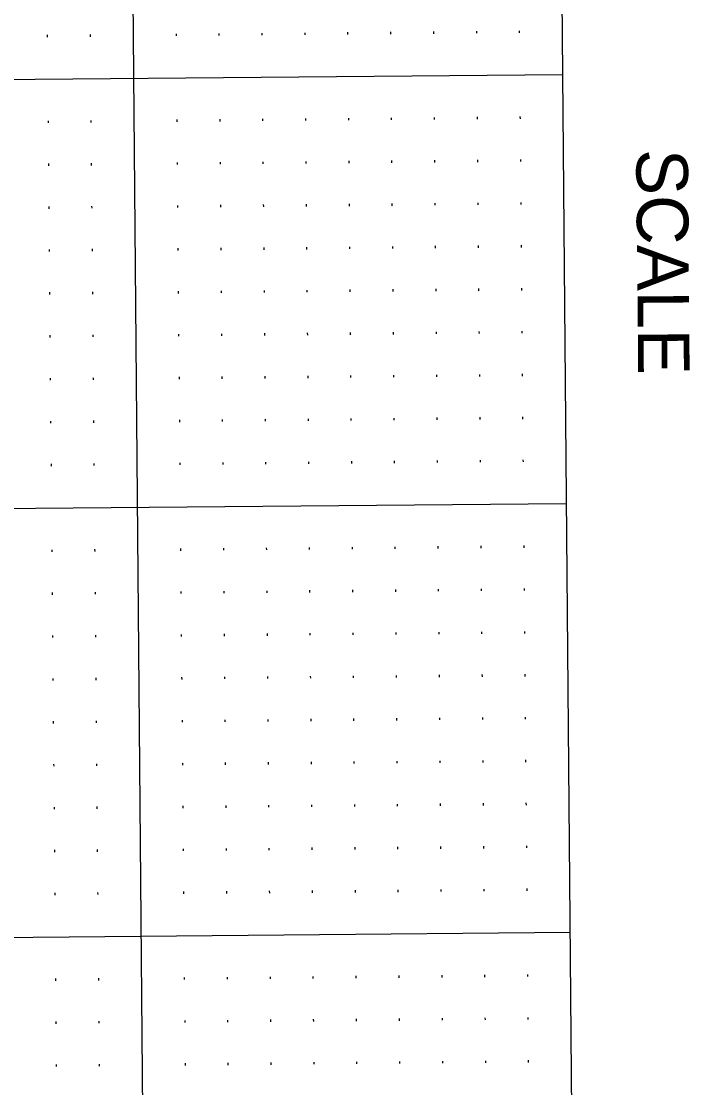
# Model space of a CAD drawing. Extents: x 2149873 to 2152007, y 140538 to 142349.
# Drawn here: x 2150424.8 to 2150502.7, y 140658.5 to 140782.7 of the extents above; entities that cross this region are included whole.
import ezdxf

# ---------------------------------------------------------------- set-up
doc = ezdxf.new("R2010")
doc.units = 0
for name, color, linetype in [('SHT_Profile_Grid_Major', 7, 'Continuous'), ('SHT_Profile_Grid_Minor', 7, 'Continuous'), ('SHT_Scale', 7, 'Continuous'), ('SHT_Sheet_Border', 7, 'Continuous')]:
    doc.layers.add(name, color=color, linetype=linetype)

msp = doc.modelspace()

# ---------------------------------------------------------------- linework, layer by layer
at = {"layer": 'SHT_Profile_Grid_Major'}
for p, q in [((2150425.71, 142163.57), (2150439.49, 140588.63)), ((2150012.87, 140772.4), (2150487.85, 140776.56)), ((2150088.3, 140723.06), (2150488.29, 140726.56)), ((2150088.74, 140673.06), (2150488.73, 140676.56))]:
    msp.add_line(p, q, dxfattribs=at)
at = {"layer": 'SHT_Profile_Grid_Minor'}
for p, q in [((2150472.81, 140781.55), (2150472.81, 140781.3)), ((2150477.81, 140781.6), (2150477.81, 140781.35)), ((2150482.81, 140781.64), (2150482.81, 140781.39)), ((2150427.81, 140781.16), (2150427.81, 140780.91)), ((2150432.81, 140781.2), (2150432.81, 140780.95)), ((2150442.81, 140781.29), (2150442.81, 140781.04)), ((2150447.81, 140781.34), (2150447.81, 140781.09)), ((2150452.81, 140781.38), (2150452.81, 140781.13)), ((2150457.81, 140781.42), (2150457.81, 140781.17)), ((2150462.81, 140781.47), (2150462.81, 140781.22)), ((2150467.81, 140781.51), (2150467.81, 140781.26)), ((2150477.89, 140771.6), (2150477.9, 140771.35)), ((2150482.89, 140771.64), (2150482.9, 140771.39)), ((2150427.9, 140771.16), (2150427.9, 140770.91)), ((2150432.9, 140771.2), (2150432.9, 140770.95)), ((2150442.9, 140771.29), (2150442.9, 140771.04)), ((2150447.9, 140771.34), (2150447.9, 140771.09)), ((2150452.9, 140771.38), (2150452.9, 140771.13)), ((2150457.9, 140771.42), (2150457.9, 140771.17)), ((2150462.9, 140771.47), (2150462.9, 140771.22)), ((2150467.89, 140771.51), (2150467.9, 140771.26)), ((2150472.89, 140771.55), (2150472.9, 140771.3)), ((2150482.94, 140766.64), (2150482.94, 140766.39)), ((2150427.94, 140766.16), (2150427.94, 140765.91)), ((2150432.94, 140766.2), (2150432.94, 140765.95)), ((2150442.94, 140766.29), (2150442.94, 140766.04)), ((2150447.94, 140766.34), (2150447.94, 140766.09)), ((2150452.94, 140766.38), (2150452.94, 140766.13)), ((2150457.94, 140766.42), (2150457.94, 140766.17)), ((2150462.94, 140766.47), (2150462.94, 140766.22)), ((2150467.94, 140766.51), (2150467.94, 140766.26)), ((2150472.94, 140766.55), (2150472.94, 140766.3)), ((2150477.94, 140766.6), (2150477.94, 140766.35)), ((2150482.98, 140761.64), (2150482.98, 140761.39)), ((2150427.98, 140761.16), (2150427.99, 140760.91)), ((2150432.98, 140761.2), (2150432.99, 140760.95)), ((2150442.98, 140761.29), (2150442.99, 140761.04)), ((2150447.98, 140761.34), (2150447.99, 140761.09)), ((2150452.98, 140761.38), (2150452.99, 140761.13)), ((2150457.98, 140761.42), (2150457.99, 140761.17)), ((2150462.98, 140761.47), (2150462.98, 140761.22)), ((2150467.98, 140761.51), (2150467.98, 140761.26)), ((2150472.98, 140761.56), (2150472.98, 140761.31)), ((2150477.98, 140761.6), (2150477.98, 140761.35)), ((2150428.03, 140756.16), (2150428.03, 140755.91)), ((2150433.03, 140756.21), (2150433.03, 140755.96)), ((2150443.03, 140756.29), (2150443.03, 140756.04)), ((2150448.03, 140756.34), (2150448.03, 140756.09)), ((2150453.03, 140756.38), (2150453.03, 140756.13)), ((2150458.03, 140756.42), (2150458.03, 140756.17)), ((2150463.03, 140756.47), (2150463.03, 140756.22)), ((2150468.03, 140756.51), (2150468.03, 140756.26)), ((2150473.03, 140756.56), (2150473.03, 140756.31)), ((2150478.03, 140756.6), (2150478.03, 140756.35)), ((2150483.03, 140756.64), (2150483.03, 140756.39)), ((2150428.07, 140751.16), (2150428.07, 140750.91)), ((2150433.07, 140751.21), (2150433.07, 140750.96)), ((2150443.07, 140751.29), (2150443.07, 140751.04)), ((2150448.07, 140751.34), (2150448.07, 140751.09)), ((2150453.07, 140751.38), (2150453.07, 140751.13)), ((2150458.07, 140751.42), (2150458.07, 140751.17)), ((2150463.07, 140751.47), (2150463.07, 140751.22)), ((2150468.07, 140751.51), (2150468.07, 140751.26)), ((2150473.07, 140751.56), (2150473.07, 140751.31)), ((2150478.07, 140751.6), (2150478.07, 140751.35)), ((2150483.07, 140751.64), (2150483.07, 140751.39)), ((2150428.12, 140746.16), (2150428.12, 140745.91)), ((2150433.12, 140746.21), (2150433.12, 140745.96)), ((2150443.11, 140746.29), (2150443.12, 140746.04)), ((2150448.11, 140746.34), (2150448.12, 140746.09)), ((2150453.11, 140746.38), (2150453.12, 140746.13)), ((2150458.11, 140746.42), (2150458.12, 140746.17)), ((2150463.11, 140746.47), (2150463.12, 140746.22)), ((2150468.11, 140746.51), (2150468.12, 140746.26)), ((2150473.11, 140746.56), (2150473.12, 140746.31)), ((2150478.11, 140746.6), (2150478.12, 140746.35)), ((2150483.11, 140746.64), (2150483.12, 140746.39)), ((2150428.16, 140741.16), (2150428.16, 140740.91)), ((2150433.16, 140741.21), (2150433.16, 140740.96)), ((2150443.16, 140741.29), (2150443.16, 140741.04)), ((2150448.16, 140741.34), (2150448.16, 140741.09)), ((2150453.16, 140741.38), (2150453.16, 140741.13)), ((2150458.16, 140741.42), (2150458.16, 140741.17)), ((2150463.16, 140741.47), (2150463.16, 140741.22)), ((2150468.16, 140741.51), (2150468.16, 140741.26)), ((2150473.16, 140741.56), (2150473.16, 140741.31)), ((2150478.16, 140741.6), (2150478.16, 140741.35)), ((2150483.16, 140741.64), (2150483.16, 140741.39)), ((2150428.2, 140736.16), (2150428.2, 140735.91)), ((2150433.2, 140736.21), (2150433.2, 140735.96)), ((2150443.2, 140736.29), (2150443.2, 140736.04)), ((2150448.2, 140736.34), (2150448.2, 140736.09)), ((2150453.2, 140736.38), (2150453.2, 140736.13)), ((2150458.2, 140736.42), (2150458.2, 140736.17)), ((2150463.2, 140736.47), (2150463.2, 140736.22)), ((2150468.2, 140736.51), (2150468.2, 140736.26)), ((2150473.2, 140736.56), (2150473.2, 140736.31)), ((2150478.2, 140736.6), (2150478.2, 140736.35)), ((2150483.2, 140736.64), (2150483.2, 140736.39)), ((2150428.25, 140731.16), (2150428.25, 140730.91)), ((2150433.25, 140731.21), (2150433.25, 140730.96)), ((2150443.25, 140731.29), (2150443.25, 140731.04)), ((2150448.25, 140731.34), (2150448.25, 140731.09)), ((2150453.25, 140731.38), (2150453.25, 140731.13)), ((2150458.25, 140731.42), (2150458.25, 140731.17)), ((2150463.25, 140731.47), (2150463.25, 140731.22)), ((2150468.25, 140731.51), (2150468.25, 140731.26)), ((2150473.24, 140731.56), (2150473.25, 140731.31)), ((2150478.24, 140731.6), (2150478.25, 140731.35)), ((2150483.24, 140731.64), (2150483.25, 140731.39)), ((2150428.33, 140721.16), (2150428.34, 140720.91)), ((2150433.33, 140721.21), (2150433.34, 140720.96)), ((2150443.33, 140721.29), (2150443.34, 140721.04)), ((2150448.33, 140721.34), (2150448.34, 140721.09)), ((2150453.33, 140721.38), (2150453.34, 140721.13)), ((2150458.33, 140721.43), (2150458.34, 140721.18)), ((2150463.33, 140721.47), (2150463.33, 140721.22)), ((2150468.33, 140721.51), (2150468.33, 140721.26)), ((2150473.33, 140721.56), (2150473.33, 140721.31)), ((2150478.33, 140721.6), (2150478.33, 140721.35)), ((2150483.33, 140721.64), (2150483.33, 140721.39)), ((2150428.38, 140716.16), (2150428.38, 140715.91)), ((2150433.38, 140716.21), (2150433.38, 140715.96)), ((2150443.38, 140716.29), (2150443.38, 140716.04)), ((2150448.38, 140716.34), (2150448.38, 140716.09)), ((2150453.38, 140716.38), (2150453.38, 140716.13)), ((2150458.38, 140716.43), (2150458.38, 140716.18)), ((2150463.38, 140716.47), (2150463.38, 140716.22)), ((2150468.38, 140716.51), (2150468.38, 140716.26)), ((2150473.38, 140716.56), (2150473.38, 140716.31)), ((2150478.38, 140716.6), (2150478.38, 140716.35)), ((2150483.38, 140716.64), (2150483.38, 140716.39)), ((2150428.42, 140711.16), (2150428.42, 140710.91)), ((2150433.42, 140711.21), (2150433.42, 140710.96)), ((2150443.42, 140711.29), (2150443.42, 140711.04)), ((2150448.42, 140711.34), (2150448.42, 140711.09)), ((2150453.42, 140711.38), (2150453.42, 140711.13)), ((2150458.42, 140711.43), (2150458.42, 140711.18)), ((2150463.42, 140711.47), (2150463.42, 140711.22)), ((2150468.42, 140711.51), (2150468.42, 140711.26)), ((2150473.42, 140711.56), (2150473.42, 140711.31)), ((2150478.42, 140711.6), (2150478.42, 140711.35)), ((2150483.42, 140711.64), (2150483.42, 140711.39)), ((2150428.47, 140706.16), (2150428.47, 140705.91)), ((2150433.47, 140706.21), (2150433.47, 140705.96)), ((2150443.46, 140706.29), (2150443.47, 140706.04)), ((2150448.46, 140706.34), (2150448.47, 140706.09)), ((2150453.46, 140706.38), (2150453.47, 140706.13)), ((2150458.46, 140706.43), (2150458.47, 140706.18)), ((2150463.46, 140706.47), (2150463.47, 140706.22)), ((2150468.46, 140706.51), (2150468.47, 140706.26)), ((2150473.46, 140706.56), (2150473.47, 140706.31)), ((2150478.46, 140706.6), (2150478.47, 140706.35)), ((2150483.46, 140706.64), (2150483.47, 140706.39)), ((2150428.51, 140701.16), (2150428.51, 140700.91)), ((2150433.51, 140701.21), (2150433.51, 140700.96)), ((2150443.51, 140701.29), (2150443.51, 140701.04)), ((2150448.51, 140701.34), (2150448.51, 140701.09)), ((2150453.51, 140701.38), (2150453.51, 140701.13)), ((2150458.51, 140701.43), (2150458.51, 140701.18)), ((2150463.51, 140701.47), (2150463.51, 140701.22)), ((2150468.51, 140701.51), (2150468.51, 140701.26)), ((2150473.51, 140701.56), (2150473.51, 140701.31)), ((2150478.51, 140701.6), (2150478.51, 140701.35)), ((2150483.51, 140701.64), (2150483.51, 140701.39)), ((2150428.55, 140696.16), (2150428.56, 140695.91)), ((2150433.55, 140696.21), (2150433.55, 140695.96)), ((2150443.55, 140696.29), (2150443.55, 140696.04)), ((2150448.55, 140696.34), (2150448.55, 140696.09)), ((2150453.55, 140696.38), (2150453.55, 140696.13)), ((2150458.55, 140696.43), (2150458.55, 140696.18)), ((2150463.55, 140696.47), (2150463.55, 140696.22)), ((2150468.55, 140696.51), (2150468.55, 140696.26)), ((2150473.55, 140696.56), (2150473.55, 140696.31)), ((2150478.55, 140696.6), (2150478.55, 140696.35)), ((2150483.55, 140696.65), (2150483.55, 140696.4)), ((2150428.6, 140691.16), (2150428.6, 140690.91)), ((2150433.6, 140691.21), (2150433.6, 140690.96)), ((2150443.6, 140691.3), (2150443.6, 140691.05)), ((2150448.6, 140691.34), (2150448.6, 140691.09)), ((2150453.6, 140691.38), (2150453.6, 140691.13)), ((2150458.6, 140691.43), (2150458.6, 140691.18)), ((2150463.6, 140691.47), (2150463.6, 140691.22)), ((2150468.6, 140691.51), (2150468.6, 140691.26)), ((2150473.59, 140691.56), (2150473.6, 140691.31)), ((2150478.59, 140691.6), (2150478.6, 140691.35)), ((2150483.59, 140691.65), (2150483.6, 140691.4)), ((2150428.64, 140686.16), (2150428.64, 140685.91)), ((2150433.64, 140686.21), (2150433.64, 140685.96)), ((2150443.64, 140686.3), (2150443.64, 140686.05)), ((2150448.64, 140686.34), (2150448.64, 140686.09)), ((2150453.64, 140686.38), (2150453.64, 140686.13)), ((2150458.64, 140686.43), (2150458.64, 140686.18)), ((2150463.64, 140686.47), (2150463.64, 140686.22)), ((2150468.64, 140686.51), (2150468.64, 140686.26)), ((2150473.64, 140686.56), (2150473.64, 140686.31)), ((2150478.64, 140686.6), (2150478.64, 140686.35)), ((2150483.64, 140686.65), (2150483.64, 140686.4)), ((2150428.68, 140681.16), (2150428.69, 140680.91)), ((2150433.68, 140681.21), (2150433.69, 140680.96)), ((2150443.68, 140681.3), (2150443.69, 140681.05)), ((2150448.68, 140681.34), (2150448.69, 140681.09)), ((2150453.68, 140681.38), (2150453.69, 140681.13)), ((2150458.68, 140681.43), (2150458.69, 140681.18)), ((2150463.68, 140681.47), (2150463.69, 140681.22)), ((2150468.68, 140681.51), (2150468.68, 140681.26)), ((2150473.68, 140681.56), (2150473.68, 140681.31)), ((2150478.68, 140681.6), (2150478.68, 140681.35)), ((2150483.68, 140681.65), (2150483.68, 140681.4)), ((2150428.77, 140671.16), (2150428.77, 140670.91)), ((2150433.77, 140671.21), (2150433.77, 140670.96)), ((2150443.77, 140671.3), (2150443.77, 140671.05)), ((2150448.77, 140671.34), (2150448.77, 140671.09)), ((2150453.77, 140671.38), (2150453.77, 140671.13)), ((2150458.77, 140671.43), (2150458.77, 140671.18)), ((2150463.77, 140671.47), (2150463.77, 140671.22)), ((2150468.77, 140671.51), (2150468.77, 140671.26)), ((2150473.77, 140671.56), (2150473.77, 140671.31)), ((2150478.77, 140671.6), (2150478.77, 140671.35)), ((2150483.77, 140671.65), (2150483.77, 140671.4)), ((2150428.82, 140666.16), (2150428.82, 140665.91)), ((2150433.82, 140666.21), (2150433.82, 140665.96)), ((2150443.82, 140666.3), (2150443.82, 140666.05)), ((2150448.81, 140666.34), (2150448.82, 140666.09)), ((2150453.81, 140666.38), (2150453.82, 140666.13)), ((2150458.81, 140666.43), (2150458.82, 140666.18)), ((2150463.81, 140666.47), (2150463.82, 140666.22)), ((2150468.81, 140666.51), (2150468.82, 140666.26)), ((2150473.81, 140666.56), (2150473.82, 140666.31)), ((2150478.81, 140666.6), (2150478.82, 140666.35)), ((2150483.81, 140666.65), (2150483.82, 140666.4)), ((2150428.86, 140661.16), (2150428.86, 140660.91)), ((2150433.86, 140661.21), (2150433.86, 140660.96)), ((2150443.86, 140661.3), (2150443.86, 140661.05)), ((2150448.86, 140661.34), (2150448.86, 140661.09)), ((2150453.86, 140661.38), (2150453.86, 140661.13)), ((2150458.86, 140661.43), (2150458.86, 140661.18)), ((2150463.86, 140661.47), (2150463.86, 140661.22)), ((2150468.86, 140661.52), (2150468.86, 140661.27)), ((2150473.86, 140661.56), (2150473.86, 140661.31)), ((2150478.86, 140661.6), (2150478.86, 140661.35)), ((2150483.86, 140661.65), (2150483.86, 140661.4))]:
    msp.add_line(p, q, dxfattribs=at)
at = {"layer": 'SHT_Sheet_Border'}
msp.add_line((2150475.71, 142164.01), (2150489.49, 140589.07), dxfattribs=at)

# ---------------------------------------------------------------- texts
at = {"layer": 'SHT_Scale'}
msp.add_text('SCALE', height=6, rotation=270.5015, dxfattribs=at).set_placement((2150496.44, 140767.83))

doc.saveas('drawing.dxf')
